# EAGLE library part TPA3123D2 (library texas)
25-W STEREO CLASS-D AUDIO POWER AMPLIFIER Please INVOKE gate EXP, set DRC-Clearance | Same signals | SMD - SMD = 0 Source: http://focus.ti.com/lit/ds/symlink/tpa3123d2.pdf
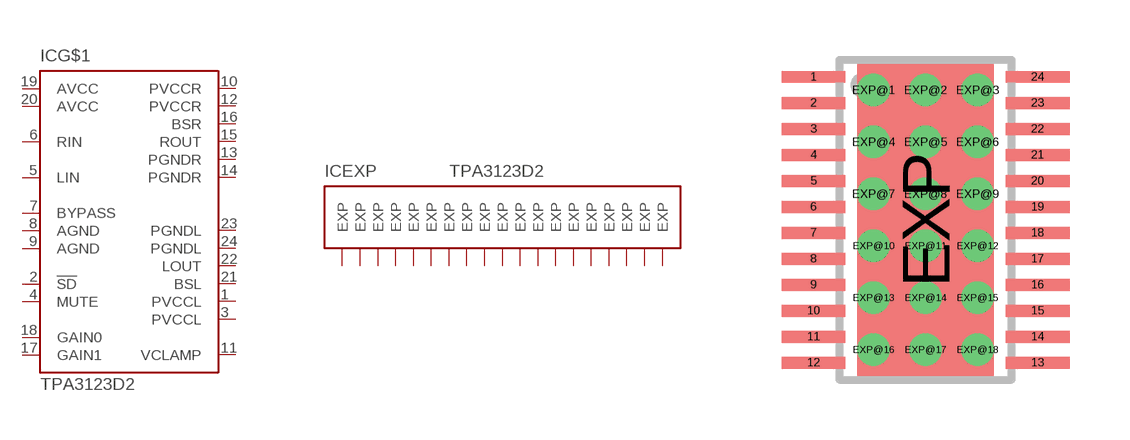
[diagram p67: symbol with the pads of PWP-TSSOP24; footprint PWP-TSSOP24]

Designator prefix IC; gates G$1=TPA3123D2 EXP=EXP19

## TPA3123D2 (MPN: TPA3123D2PWP; OC_FARNELL: 1632099; OC_NEWARK: 53M3994)  [PWP-TSSOP24]
1  G$1:PVCCL  in
2  G$1:!SD  in
3  G$1:PVCCL  in
4  G$1:MUTE  in
5  G$1:LIN  in
6  G$1:RIN  in
7  G$1:BYPASS  in
8  G$1:AGND  in
9  G$1:AGND  in
10  G$1:PVCCR  in
11  G$1:VCLAMP  in
12  G$1:PVCCR  in
13  G$1:PGNDR  in
14  G$1:PGNDR  in
15  G$1:ROUT  out
16  G$1:BSR  pas
17  G$1:GAIN1  in
18  G$1:GAIN0  in
19  G$1:AVCC  in
20  G$1:AVCC  in
21  G$1:BSL  pas
22  G$1:LOUT  out
23  G$1:PGNDL  in
24  G$1:PGNDL  in
EXP  EXP:EXP  pas
EXP@1  EXP:EXP  pas
EXP@2  EXP:EXP  pas
EXP@3  EXP:EXP  pas
EXP@4  EXP:EXP  pas
EXP@5  EXP:EXP  pas
EXP@6  EXP:EXP  pas
EXP@7  EXP:EXP  pas
EXP@8  EXP:EXP  pas
EXP@9  EXP:EXP  pas
EXP@10  EXP:EXP  pas
EXP@11  EXP:EXP  pas
EXP@12  EXP:EXP  pas
EXP@13  EXP:EXP  pas
EXP@14  EXP:EXP  pas
EXP@15  EXP:EXP  pas
EXP@16  EXP:EXP  pas
EXP@17  EXP:EXP  pas
EXP@18  EXP:EXP  pas

## Footprint PWP-TSSOP24 (pad centres in mm)
PWP (R-PDSO-G24) PowerPAD TM Source: http://focus.ti.com/lit/ds/symlink/tpa3123d2.pdf
smd 1.6 x 0.3: 1 -2.8,3.575; 2 -2.8,2.925; 3 -2.8,2.275; 4 -2.8,1.625; 5 -2.8,0.975; 6 -2.8,0.325; 7 -2.8,-0.325; 8 -2.8,-0.975; 9 -2.8,-1.625; 10 -2.8,-2.275; 11 -2.8,-2.925; 12 -2.8,-3.575; 13 2.8,-3.575; 14 2.8,-2.925; 15 2.8,-2.275; 16 2.8,-1.625; 17 2.8,-0.975; 18 2.8,-0.325; 19 2.8,0.325; 20 2.8,0.975; 21 2.8,1.625; 22 2.8,2.275; 23 2.8,2.925; 24 2.8,3.575
smd 3.4 x 7.8: EXP 0,0
drill 0.3 pad 0.7 round: EXP@1 -1.3,3.25; EXP@2 0,3.25; EXP@3 1.3,3.25; EXP@4 -1.3,1.95; EXP@5 0,1.95; EXP@6 1.3,1.95; EXP@7 -1.3,0.65; EXP@8 0,0.65; EXP@9 1.3,0.65; EXP@10 -1.3,-0.65; EXP@11 0,-0.65; EXP@12 1.3,-0.65; EXP@13 -1.3,-1.95; EXP@14 0,-1.95; EXP@15 1.3,-1.95; EXP@16 -1.3,-3.25; EXP@17 0,-3.25; EXP@18 1.3,-3.25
